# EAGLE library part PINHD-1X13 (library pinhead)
PIN HEADER
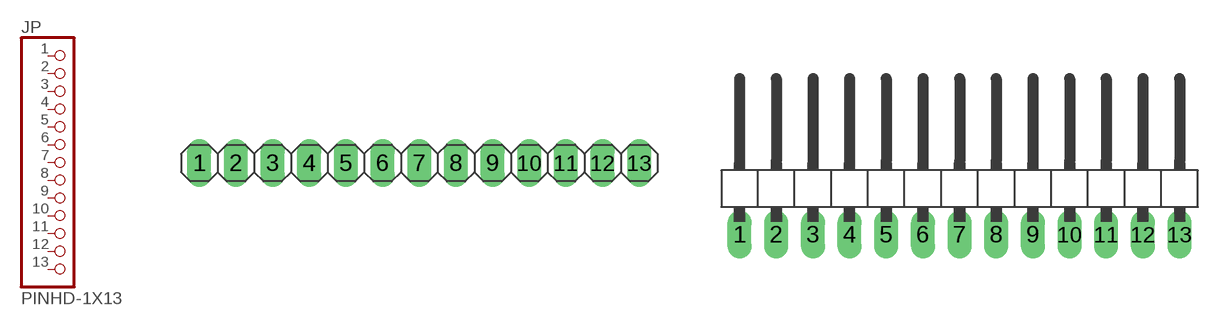
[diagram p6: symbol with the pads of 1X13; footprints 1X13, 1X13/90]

Designator prefix JP

## PINHD-1X13  [1X13]
1  1  pas
2  2  pas
3  3  pas
4  4  pas
5  5  pas
6  6  pas
7  7  pas
8  8  pas
9  9  pas
10  10  pas
11  11  pas
12  12  pas
13  13  pas

## PINHD-1X13/90  [1X13/90]
Pads as for 1X13

## Footprint 1X13 (pad centres in mm)
PIN HEADER
drill 1.016 pad 1.67 long: 1 -15.24,0; 2 -12.7,0; 3 -10.16,0; 4 -7.62,0; 5 -5.08,0; 6 -2.54,0; 7 0,0; 8 2.54,0; 9 5.08,0; 10 7.62,0; 11 10.16,0; 12 12.7,0; 13 15.24,0

## Footprint 1X13/90 (pad centres in mm)
PIN HEADER
drill 1.016 pad 1.67 long: 1 -15.24,-3.81; 2 -12.7,-3.81; 3 -10.16,-3.81; 4 -7.62,-3.81; 5 -5.08,-3.81; 6 -2.54,-3.81; 7 0,-3.81; 8 2.54,-3.81; 9 5.08,-3.81; 10 7.62,-3.81; 11 10.16,-3.81; 12 12.7,-3.81; 13 15.24,-3.81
